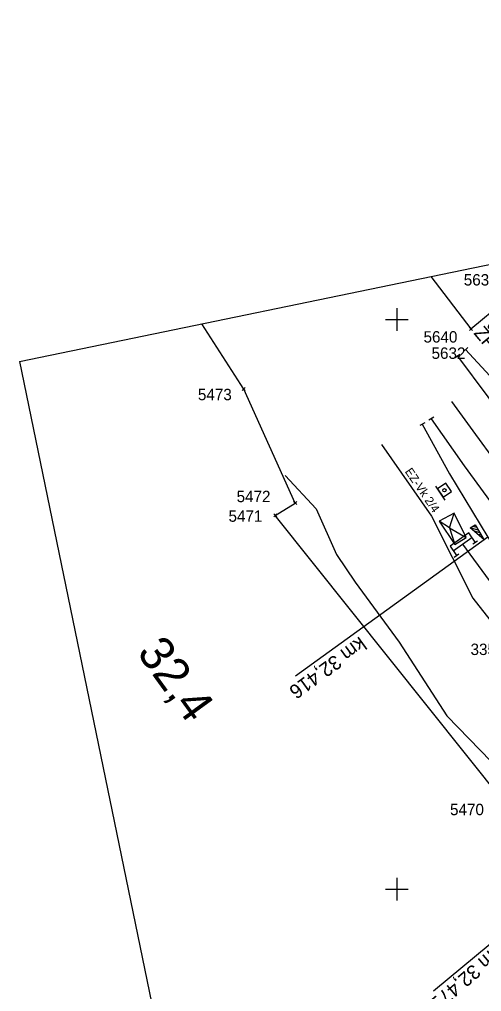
# Model space of a CAD drawing. Extents: x -804166 to -803706, y -1151030 to -1150147.
# Drawn here: x -804166.3 to -804085.1, y -1150318 to -1150147.3 of the extents above; entities that cross this region are included whole.
import ezdxf

# ---------------------------------------------------------------- set-up
doc = ezdxf.new("R2010")
doc.units = 0
for name, color, linetype in [('0381KM032-037P - Vrstva 1', 7, 'Continuous'), ('0381KM032-037P - Vrstva 15', 7, 'Continuous'), ('0381KM032-037P - Vrstva 2', 7, 'Continuous'), ('0381KM032-037P - Vrstva 3', 7, 'Continuous'), ('0381KM032-037P - Vrstva 49', 7, 'Continuous'), ('0381KM032-037P - Vrstva 7', 7, 'Continuous'), ('0381KM032-037P - Vrstva 9', 7, 'Continuous'), ('DZ_CD - CD_čísla', 7, 'Continuous'), ('formát', 7, 'Continuous'), ('krizky_1000 - Vrstva 1', 7, 'Continuous'), ('szdc - hran DP', 7, 'Continuous'), ('szdc - szdc_cislo', 7, 'Continuous'), ('szdc - szdc_krizek', 7, 'Continuous'), ('vyt_sit - stávající', 7, 'Continuous')]:
    doc.layers.add(name, color=color, linetype=linetype)

msp = doc.modelspace()

# ---------------------------------------------------------------- linework, layer by layer
at = {"layer": '0381KM032-037P - Vrstva 1'}
for points in [[(-804089.35, -1150206.44), (-804078.67, -1150220.7), (-804069.15, -1150233.38), (-804067.86, -1150235.11), (-804059.28, -1150246.53), (-804058.07, -1150248.16), (-804048.7, -1150260.65), (-804037.85, -1150275.13), (-804021.63, -1150296.76), (-804006.14, -1150317.34), (-803988.98, -1150340.29), (-803981.9, -1150349.73)], [(-804087.93, -1150205.28), (-804078.71, -1150215.28), (-804072.37, -1150222.52), (-804072.08, -1150222.85), (-804071.47, -1150223.58), (-804065.48, -1150230.82), (-804059.47, -1150238.51), (-804055.55, -1150243.68), (-804054.36, -1150245.27), (-804043.89, -1150259.22), (-804035.37, -1150270.61), (-804034.4, -1150271.93), (-804017.97, -1150293.92), (-804002.6, -1150314.46), (-803985.38, -1150337.43), (-803955.87, -1150376.72)], [(-804090.39, -1150214.38), (-804086.65, -1150219.55), (-804073.82, -1150237.11), (-804072.56, -1150238.83), (-804064.05, -1150250.31), (-804062.81, -1150251.97), (-804052.29, -1150266.05), (-804042.5, -1150279.11), (-804026.55, -1150300.33), (-804011.27, -1150320.63), (-803993.37, -1150344.49), (-803965.17, -1150382.07), (-803953.84, -1150397.19)], [(-804095.55, -1150218.38), (-804090.74, -1150227.08), (-804084.01, -1150238.21), (-804078.76, -1150245.78), (-804072.11, -1150254.85), (-804070.85, -1150256.55), (-804059.97, -1150271.29), (-804049.56, -1150285.37), (-804034.13, -1150306.22), (-804018.79, -1150326.86), (-804001.18, -1150350.63), (-803980.37, -1150378.68), (-803972.82, -1150388.42), (-803965.21, -1150397.6)], [(-804093.97, -1150217.42), (-804088.17, -1150225.67), (-804077.51, -1150240.28), (-804068.52, -1150252.21), (-804067.31, -1150253.81), (-804055.01, -1150270.12), (-804046.09, -1150281.93), (-804030.05, -1150303.21), (-804014.76, -1150323.52), (-803996.92, -1150347.35), (-803968.88, -1150385.42), (-803942.6, -1150419.03)], [(-804088.45, -1150239.45), (-804070.36, -1150264.07), (-804054.98, -1150285.05), (-804052.95, -1150287.79), (-804037.56, -1150308.64), (-804021.87, -1150329.91), (-804004.48, -1150353.56), (-803990.76, -1150372.09)]]:
    msp.add_lwpolyline(points, dxfattribs=at)
at = {"layer": '0381KM032-037P - Vrstva 15'}
for p, q in [((-804090.09, -1150240.6), (-804086.81, -1150238.3)), ((-804086.65, -1150239.41), (-804085.83, -1150238.83)), ((-804089.92, -1150241.7), (-804089.1, -1150241.13))]:
    msp.add_line(p, q, dxfattribs=at)
msp.add_lwpolyline([(-804086.24, -1150239.12), (-804087.39, -1150237.48), (-804090.66, -1150239.78), (-804089.51, -1150241.41)], dxfattribs=at)
at = {"layer": '0381KM032-037P - Vrstva 2'}
for p, q in [((-804087.56, -1150204.95), (-804088.29, -1150205.62)), ((-804088.95, -1150206.14), (-804089.74, -1150206.75)), ((-804095.11, -1150218.14), (-804095.99, -1150218.62)), ((-804093.53, -1150217.18), (-804094.41, -1150217.66))]:
    msp.add_line(p, q, dxfattribs=at)
at = {"layer": '0381KM032-037P - Vrstva 3'}
for p, q in [((-804091.42, -1150228.76), (-804092.88, -1150229.76)), ((-804090.42, -1150230.22), (-804091.42, -1150228.76)), ((-804093.21, -1150229.27), (-804091.55, -1150231.71)), ((-804092.88, -1150229.76), (-804091.88, -1150231.22)), ((-804091.88, -1150231.22), (-804090.42, -1150230.22)), ((-804085.69, -1150236.97), (-804087.02, -1150236.65)), ((-804085.97, -1150236.52), (-804086.71, -1150236.34)), ((-804085.42, -1150237.43), (-804086.38, -1150237.19)), ((-804086.24, -1150236.07), (-804086.26, -1150236.06)), ((-804084.01, -1150238.21), (-804117.81, -1150262.63)), ((-804085.14, -1150237.88), (-804085.74, -1150237.73))]:
    msp.add_line(p, q, dxfattribs=at)
msp.add_lwpolyline([(-804084.7, -1150238.62), (-804087.1, -1150236.57), (-804086.25, -1150236.06), (-804084.7, -1150238.62)], dxfattribs=at)
msp.add_circle((-804091.65, -1150229.99), 0.296, dxfattribs=at)
at = {"layer": '0381KM032-037P - Vrstva 49'}
for q in [(-804089.96, -1150233.98), (-804092.55, -1150235.38), (-804087.81, -1150238.25), (-804089.82, -1150239.52)]:
    msp.add_line((-804090.75, -1150236.55), q, dxfattribs=at)
for points in [[(-804102.72, -1150221.96), (-804093.91, -1150234.53), (-804086.64, -1150248.91), (-804067.58, -1150273.2)], [(-804119.6, -1150227.37), (-804114.18, -1150233.24), (-804110.61, -1150241.24), (-804107.35, -1150246.09), (-804099.61, -1150256.67), (-804091.21, -1150269.57), (-804073.78, -1150287.54), (-804061.47, -1150301.24), (-804053.54, -1150315.4), (-804051.02, -1150318.44), (-804043.41, -1150327.56), (-804036.34, -1150339.31), (-804033.47, -1150348.91), (-804032.83, -1150355.72)], [(-804089.82, -1150239.52), (-804087.81, -1150238.25), (-804089.96, -1150233.98), (-804092.55, -1150235.38), (-804089.82, -1150239.52)]]:
    msp.add_lwpolyline(points, dxfattribs=at)
at = {"layer": '0381KM032-037P - Vrstva 9'}
msp.add_line((-804041.91, -1150275.08), (-804093.56, -1150317.87), dxfattribs=at)
at = {"layer": 'formát'}
for q in [(-803875.43, -1150147.35), (-804123.84, -1150413.06)]:
    msp.add_line((-804166.3, -1150207.4), q, dxfattribs=at)
at = {"layer": 'krizky_1000 - Vrstva 1'}
for points in [[(-804100, -1150198), (-804100, -1150202)], [(-804102, -1150200), (-804098, -1150200)], [(-804100, -1150298), (-804100, -1150302)], [(-804102, -1150300), (-804098, -1150300)]]:
    msp.add_lwpolyline(points, dxfattribs=at)
at = {"layer": 'szdc - hran DP'}
for p, q in [((-804094.06, -1150192.49), (-804087, -1150201.67)), ((-804087, -1150201.67), (-804080.94, -1150196.58)), ((-804126.9, -1150212.23), (-804134.27, -1150200.79)), ((-804117.86, -1150232.22), (-804126.9, -1150212.23)), ((-804121.35, -1150234.4), (-804117.86, -1150232.22)), ((-804081.21, -1150284.7), (-804121.35, -1150234.4))]:
    msp.add_line(p, q, dxfattribs=at)
at = {"layer": 'szdc - szdc_krizek'}
for p, q in [((-804086.73, -1150201.94), (-804087.27, -1150201.41)), ((-804087.27, -1150201.94), (-804086.73, -1150201.41)), ((-804126.64, -1150212.5), (-804127.17, -1150211.97)), ((-804127.17, -1150212.5), (-804126.64, -1150211.97)), ((-804117.59, -1150232.49), (-804118.13, -1150231.96)), ((-804118.13, -1150232.49), (-804117.59, -1150231.96)), ((-804121.08, -1150234.67), (-804121.62, -1150234.14)), ((-804121.62, -1150234.67), (-804121.08, -1150234.14))]:
    msp.add_line(p, q, dxfattribs=at)

# ---------------------------------------------------------------- texts
at = {"layer": '0381KM032-037P - Vrstva 3'}
for s, height, rotation, p in [('EZ-Vk 2/4', 1.5, 304.3062, (-804098.66, -1150226.7)), ('km 32,416', 2.5, 216.1512, (-804106.54, -1150255.55))]:
    msp.add_text(s, height=height, rotation=rotation, dxfattribs=at).set_placement(p)
at = {"layer": '0381KM032-037P - Vrstva 7'}
msp.add_text('32,4', height=6, rotation=306.0318, dxfattribs=at).set_placement((-804145.79, -1150258.51))
at = {"layer": '0381KM032-037P - Vrstva 9'}
msp.add_text('km 32,471', height=2.5, rotation=220.7607, dxfattribs=at).set_placement((-804082.58, -1150309.5))
at = {"layer": 'DZ_CD - CD_čísla'}
msp.add_text('335', height=2, dxfattribs=at).set_placement((-804087.06, -1150258.9))
at = {"layer": 'szdc - szdc_cislo'}
for s, p in [('5637', (-804088.25, -1150194.05)), ('5640', (-804095.32, -1150204.06)), ('5632', (-804093.91, -1150206.92)), ('5473', (-804134.95, -1150214.18)), ('5472', (-804128.15, -1150232.07)), ('5471', (-804129.57, -1150235.51)), ('5470', (-804090.66, -1150287.01))]:
    msp.add_text(s, height=2, dxfattribs=at).set_placement(p)
at = {"layer": 'vyt_sit - stávající'}
msp.add_text('ŽP 754', height=2.4, rotation=310, dxfattribs=at).set_placement((-804086.61, -1150202.44))

doc.saveas('drawing.dxf')
